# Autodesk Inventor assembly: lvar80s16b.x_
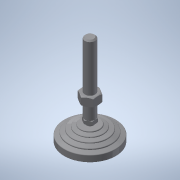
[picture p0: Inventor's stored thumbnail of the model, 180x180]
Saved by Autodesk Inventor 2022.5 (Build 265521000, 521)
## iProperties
Part Number: lvar80s16b.x_
Material: 一般
Document SubType Name: Assembly
Designer: ImaoCorp
Sending System: SOLIDWORKS 2017-2017317
MC: AMD64
MC_MODEL: Intel64 Family 6 Model 60 Stepping 3, GenuineIntel
OS: Windows_NT
FRU: Parasolid Version 29.0, build 201,  4-17-2017
FORMAT: text
GUISE: transmit
KEY: lvar80s16b
FILE: lvar80s16b.x_t
DATE: Mon Jul 01 18:16:07 2019
Author: ImaoCorp
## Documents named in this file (3)
- X:\14_SW2022-Inv2022\00_全2023-1023新製品(TCC)まで\l\lvar80s16b\LVAR80S16B.iam
- X:\14_SW2022-Inv2022\00_全2023-1023新製品(TCC)まで\l\lvar80s16b\lvar80s16b_01.ipt
- X:\14_SW2022-Inv2022\00_全2023-1023新製品(TCC)まで\l\lvar80s16b\lvar80s16b_02.ipt
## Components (2 placed, 2 different names)
1. lvar80s16b_01
2. lvar80s16b_02
